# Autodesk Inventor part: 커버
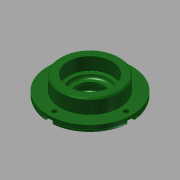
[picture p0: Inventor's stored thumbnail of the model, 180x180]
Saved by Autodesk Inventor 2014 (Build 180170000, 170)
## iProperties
Company: 한국ATC센터
Created: 2016-04
Part Number: 커버
Document SubType Name: Modeling
Designer: mdu
Density: 7.86 g/cm^3
Mass: 351.567 g
Surface Area: 161.165 cm^2
Volume: 44.7286 cm^3
Material: 강철, 연강
Appearance: 진녹색
Author: mdu
Revision Number: 1
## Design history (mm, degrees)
sketch "스케치1"
  geometry: C1 r 38 at (0, 0); 1 further point
  constraints: 1 centre point, 1 coincident
  dimensions: "d0" = 76 diameter of C1
extrude "돌출1" new body sketch "스케치1" distance "d1" = 7; taper "d2" = 0 deg
sketch "스케치2"
  geometry: C1 r 27 at (0, 0); 1 further point
  constraints: 1 centre point, 1 coincident
  dimensions: "d3" = 54 diameter of C1
extrude "돌출2" join sketch "스케치2" distance "d4" = 13; taper "d5" = 0 deg
sketch "스케치3"
  geometry: C1 r 20 at (0, 0); 1 further point
  constraints: 1 centre point, 1 coincident
  dimensions: "d6" = 40 diameter of C1
extrude "돌출3" join sketch "스케치3" distance "d7" = 5; taper "d8" = 0 deg
hole "구멍1" diameter "d11" = 25; stored, may be unused: countersink angle "d15" = 90 deg, drill point angle "d17" = 118 deg; dims "d9" = 10, "d10" = 10, "d12" = 6, "d13" = 32, "d14" = 8.3, "d16" = 8
hole "구멍2" diameter "d20" = 34; stored, may be unused: countersink angle "d24" = 90 deg, drill point angle "d26" = 0 deg; dims "d18" = 10, "d19" = 10, "d21" = 6, "d22" = 40, "d23" = 12, "d25" = 3
fillet "모깎기2" dims "d34" = 3
fillet "모깎기1" dims "d27" = 0.3
chamfer "모따기1" distance "d28" = 1; stored, may be unused: second distance "d29" = 2, angle "d30" = 45 deg
chamfer "모따기2" distance "d31" = 1.2; stored, may be unused: second distance "d32" = 2, angle "d33" = 30 deg
sketch "스케치4" dims "d35" = 65
  geometry: 3 further points
  constraints: 2 horizontal alignment, 1 coincident, 2 other
hole "구멍3" sketch "스케치4" at (32.5, 0) diameter "d36" = 4.5; stored, may be unused: countersink angle "d40" = 90 deg, drill point angle "d42" = 118 deg; dims "d37" = 6, "d38" = 8, "d39" = 4.4, "d41" = 13
sketch "스케치5"
  geometry: L1 (0, 4)-(5.5, 4); L2 (5.5, 4)-(5.5, -4); L3 (5.5, -4)-(0, -4); L4 (0, -4)-(0, 4); C1 r 2.25 at (0, 0) reference; C2 r 38 at (-32.5, 0) reference; 2 further points
  constraints: 8 end point, 3 horizontal, 2 parallel, 1 perpendicular, 1 tangent, 1 vertical alignment, 1 other
extrude "돌출4" cut sketch "스케치5" stored distance "d47" = 24.5; taper "d48" = 0 deg
node "솔리드1"
pattern_circular "원형 패턴1" dims angle "d44" = 360 deg
pattern_circular "원형 패턴2" dims angle "d50" = 360 deg
node "투영된 루프1"
